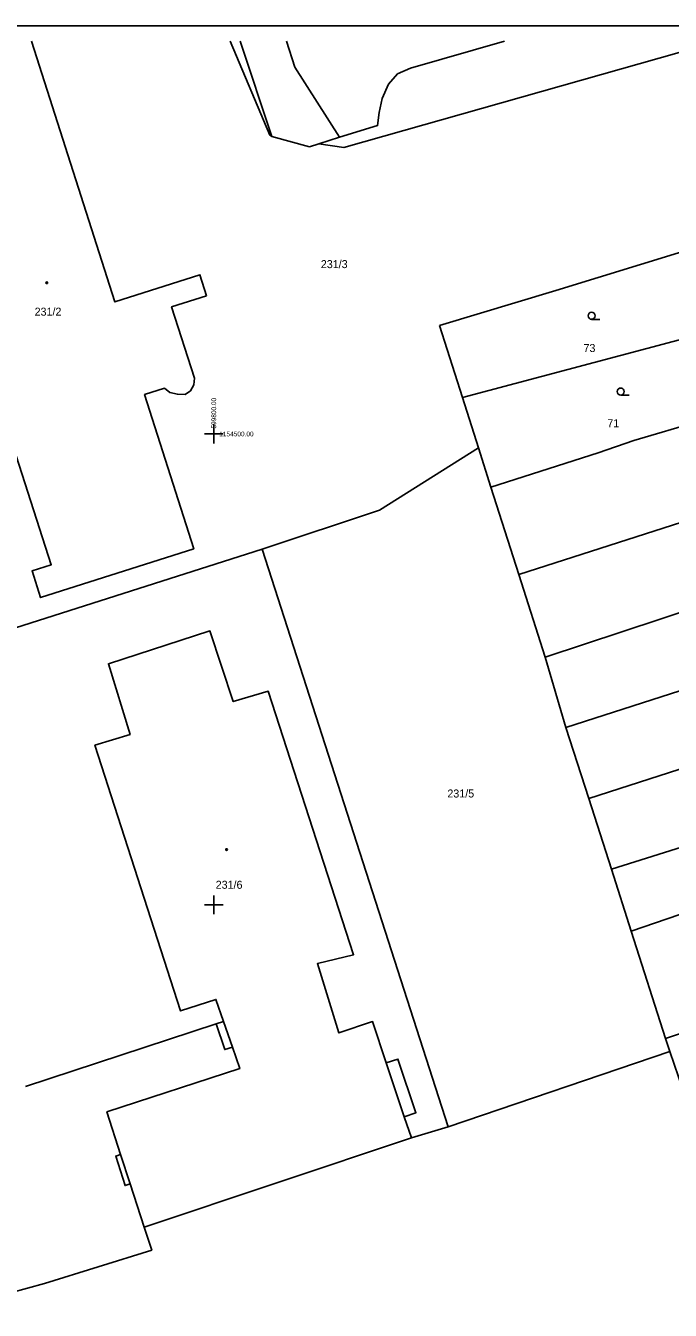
# Model space of a CAD drawing. Extents: x -599970 to -599524, y -1154772 to -1154457.
# Drawn here: x -599820 to -599751.5, y -1154593 to -1154456.7 of the extents above; entities that cross this region are included whole.
import ezdxf

# ---------------------------------------------------------------- set-up
doc = ezdxf.new("R2010")
doc.units = 0
for name, color, linetype in [('Z-KATASTRALNI MAPA', 7, 'Continuous'), ('Z-KRIZKY CTVERCOVE SITE', 7, 'Continuous'), ('Z-POPIS KRIZKU CTVERCOVE SITE', 7, 'Continuous'), ('Z-RAM ROZPISKA', 7, 'Continuous')]:
    doc.layers.add(name, color=color, linetype=linetype)

msp = doc.modelspace()

# ---------------------------------------------------------------- linework, layer by layer
at = {"layer": 'Z-KATASTRALNI MAPA'}
for p, q in [((-599797.19, -1154458.29), (-599793.83, -1154468.4)), ((-599789.84, -1154469.51), (-599793.83, -1154468.4)), ((-599786.66, -1154468.47), (-599788.85, -1154469.18)), ((-599788.85, -1154469.18), (-599789.84, -1154469.51)), ((-599759.9, -1154487.83), (-599759.02, -1154487.83)), ((-599776.06, -1154488.49), (-599773.62, -1154496.13)), ((-599746.76, -1154488.99), (-599773.62, -1154496.13)), ((-599773.62, -1154496.13), (-599771.92, -1154501.46)), ((-599756.81, -1154495.88), (-599755.93, -1154495.88)), ((-599744.26, -1154497.41), (-599755.42, -1154500.7)), ((-599771.92, -1154501.46), (-599770.58, -1154505.66)), ((-599770.58, -1154505.66), (-599767.63, -1154514.91)), ((-599767.63, -1154514.91), (-599743.14, -1154507.07)), ((-599775.14, -1154573.56), (-599794.88, -1154512.22)), ((-599728.28, -1154511.64), (-599764.83, -1154523.7)), ((-599767.63, -1154514.91), (-599764.83, -1154523.7)), ((-599716.44, -1154516.26), (-599762.63, -1154531.18)), ((-599764.83, -1154523.7), (-599762.63, -1154531.18)), ((-599714.03, -1154523.9), (-599760.21, -1154538.7)), ((-599762.63, -1154531.18), (-599760.21, -1154538.7)), ((-599711.61, -1154531.55), (-599757.79, -1154546.22)), ((-599760.21, -1154538.7), (-599757.79, -1154546.22)), ((-599757.79, -1154546.22), (-599755.69, -1154552.79)), ((-599755.69, -1154552.79), (-599752.06, -1154564.2)), ((-599752.06, -1154564.2), (-599741.96, -1154560.76)), ((-599799.76, -1154562.64), (-599820, -1154569.28)), ((-599798.97, -1154562.38), (-599799.76, -1154562.64)), ((-599798.97, -1154562.38), (-599798.03, -1154565.1)), ((-599752.06, -1154564.2), (-599751.59, -1154565.56)), ((-599751.59, -1154565.56), (-599775.14, -1154573.56)), ((-599748.83, -1154573.64), (-599751.59, -1154565.56)), ((-599781.69, -1154566.78), (-599779.78, -1154572.49)), ((-599775.14, -1154573.56), (-599779.03, -1154574.73)), ((-599779.03, -1154574.73), (-599807.4, -1154584.21)), ((-599809.89, -1154576.51), (-599808.88, -1154579.63))]:
    msp.add_line(p, q, dxfattribs=at)
for points in [[(-599843.53, -1154459.09), (-599852.7, -1154476.94), (-599830.94, -1154523.74), (-599794.88, -1154512.22)], [(-599828.94, -1154458.42), (-599828.4, -1154460.08), (-599833.99, -1154461.88), (-599817.26, -1154513.88), (-599819.29, -1154514.53), (-599818.39, -1154517.37), (-599802.13, -1154512.18), (-599807.35, -1154495.82), (-599805.22, -1154495.14)], [(-599800.76, -1154485.33), (-599801.47, -1154483.1), (-599810.5, -1154485.98), (-599819.36, -1154458.29)], [(-599793.83, -1154468.4), (-599794.06, -1154468.27), (-599798.26, -1154458.29)], [(-599792.28, -1154458.29), (-599791.39, -1154461.05), (-599786.66, -1154468.47)], [(-599788.85, -1154469.18), (-599786.21, -1154469.6), (-599746.35, -1154458.29)], [(-599786.66, -1154468.47), (-599782.62, -1154467.26), (-599782.46, -1154465.88), (-599782.13, -1154464.39), (-599781.47, -1154462.86), (-599780.5, -1154461.77), (-599779.14, -1154461.16), (-599769.14, -1154458.29)], [(-599750.2, -1154480.63), (-599763.69, -1154484.75), (-599776.06, -1154488.49)], [(-599805.22, -1154495.14), (-599804.65, -1154495.58), (-599803.86, -1154495.79), (-599803.03, -1154495.8), (-599802.49, -1154495.42), (-599802.13, -1154494.8), (-599802.06, -1154494.09), (-599804.48, -1154486.51), (-599800.76, -1154485.33)], [(-599794.88, -1154512.22), (-599782.42, -1154508.1), (-599771.92, -1154501.46)], [(-599755.42, -1154500.7), (-599759.19, -1154501.99), (-599770.58, -1154505.66)], [(-599779.03, -1154574.73), (-599779.78, -1154572.49), (-599778.54, -1154572.08), (-599780.45, -1154566.37), (-599781.69, -1154566.78), (-599783.15, -1154562.4), (-599786.72, -1154563.59), (-599789.01, -1154556.24), (-599785.17, -1154555.3), (-599794.22, -1154527.32), (-599797.93, -1154528.41), (-599800.42, -1154520.92), (-599811.19, -1154524.39), (-599808.88, -1154531.9), (-599812.62, -1154533.06), (-599803.55, -1154561.26), (-599799.77, -1154560.04), (-599798.97, -1154562.38)], [(-599709.19, -1154539.72), (-599710.84, -1154540.22), (-599745.47, -1154549.29), (-599755.69, -1154552.79)], [(-599799.76, -1154562.64), (-599798.83, -1154565.37), (-599798.03, -1154565.1)], [(-599798.03, -1154565.1), (-599797.25, -1154567.39), (-599811.35, -1154571.98), (-599809.89, -1154576.51), (-599810.41, -1154576.68), (-599809.41, -1154579.8), (-599808.88, -1154579.63), (-599807.4, -1154584.21)], [(-599807.4, -1154584.21), (-599806.58, -1154586.66), (-599817.96, -1154590.19), (-599823.43, -1154591.68)]]:
    msp.add_lwpolyline(points, dxfattribs=at)
for centre, radius in [((-599817.73, -1154483.95), 0.0875), ((-599759.9, -1154487.45), 0.375), ((-599756.81, -1154495.5), 0.375), ((-599798.65, -1154544.13), 0.0875)]:
    msp.add_circle(centre, radius, dxfattribs=at)
at = {"layer": 'Z-KRIZKY CTVERCOVE SITE'}
for p, q in [((-599800, -1154501), (-599800, -1154499)), ((-599799, -1154500), (-599801, -1154500)), ((-599800, -1154551), (-599800, -1154549)), ((-599799, -1154550), (-599801, -1154550))]:
    msp.add_line(p, q, dxfattribs=at)
at = {"layer": 'Z-RAM ROZPISKA'}
msp.add_lwpolyline([(-599876.98, -1154456.65), (-599579.98, -1154456.65), (-599579.98, -1154771.65), (-599876.98, -1154771.65)], close=True, dxfattribs=at)

# ---------------------------------------------------------------- texts
at = {"layer": 'Z-KATASTRALNI MAPA'}
for s, p in [('231/3', (-599788.64, -1154482.39)), ('231/2', (-599819.02, -1154487.44)), ('73', (-599760.76, -1154491.3)), ('71', (-599758.23, -1154499.28)), ('231/5', (-599775.21, -1154538.6)), ('231/6', (-599799.8, -1154548.29))]:
    msp.add_text(s, height=0.85, dxfattribs=at).set_placement(p)
at = {"layer": 'Z-POPIS KRIZKU CTVERCOVE SITE'}
msp.add_text('   599800.00', height=0.5, rotation=90, dxfattribs=at).set_placement((-599799.75, -1154500))
msp.add_text('   1154500.00', height=0.5, dxfattribs=at).set_placement((-599800, -1154500.25))

doc.saveas('drawing.dxf')
